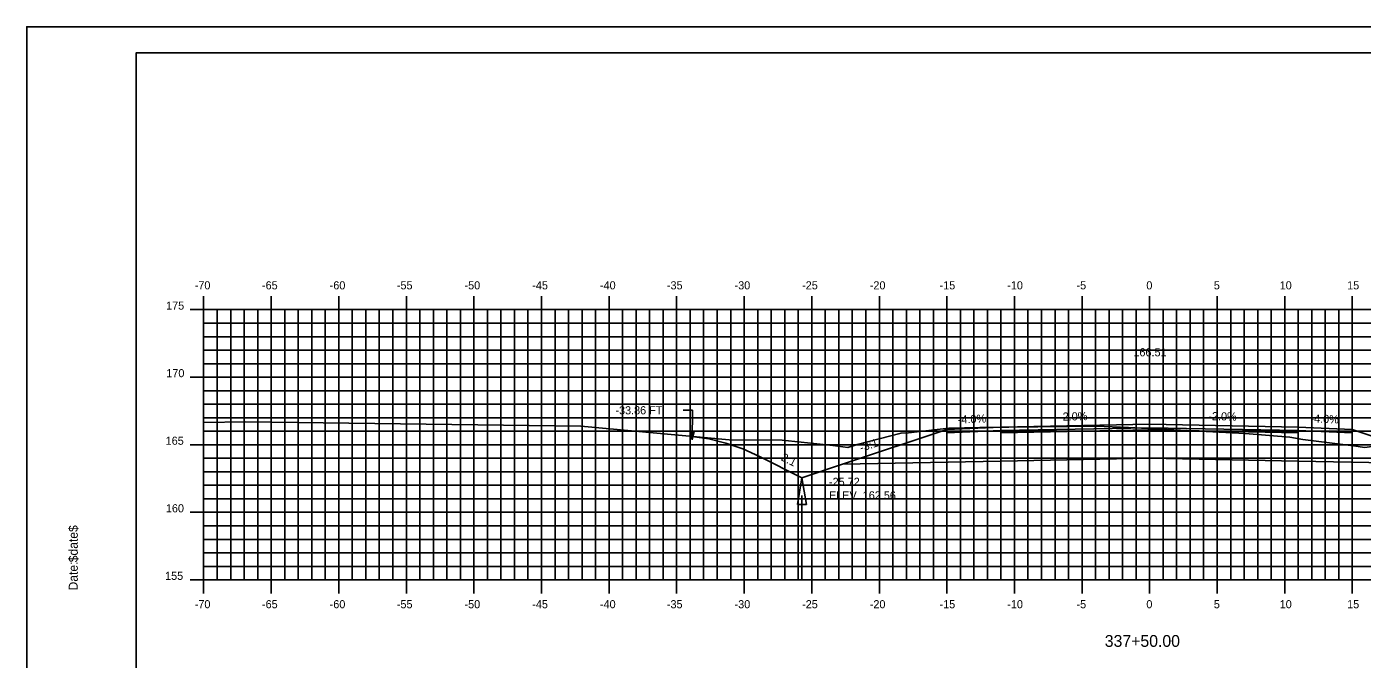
# Model space of a CAD drawing. Extents: x 1142311 to 1142481, y 608981 to 609091.
# Drawn here: x 1142311.2 to 1142410, y 609044.5 to 609091.3 of the extents above; entities that cross this region are included whole.
import ezdxf

# ---------------------------------------------------------------- set-up
doc = ezdxf.new("R2010")
doc.units = 0
for name, color, linetype in [('ANNOTATION', 7, 'Continuous'), ('BORDER', 7, 'Continuous'), ('D_Drainage_Ditch_Line', 7, 'Continuous'), ('D_Roadway_Centerline', 7, 'Continuous'), ('D_Roadway_Centerline_Text', 7, 'Continuous'), ('D_Roadway_Edge_Shoulder', 7, 'Continuous'), ('D_Roadway_Edge_TW', 7, 'Continuous'), ('D_Roadway_Pavement', 7, 'Continuous'), ('D_Roadway_SlopeLines', 7, 'Continuous'), ('D_Roadway_SubGrade', 7, 'Continuous'), ('D_Text_Standard', 7, 'Continuous'), ('H_V ANNOTATION', 7, 'Continuous'), ('MAJOR', 7, 'Continuous'), ('MINOR', 7, 'Continuous'), ('PLOT BOUNDARY', 7, 'Continuous'), ('S_Roadway_Centerline', 7, 'Continuous')]:
    doc.layers.add(name, color=color, linetype=linetype)

msp = doc.modelspace()

# ---------------------------------------------------------------- linework, layer by layer
msp.add_lwpolyline([(1142360.44, 609060.945), (1142361.69, 609060.764), (1142362.94, 609060.457), (1142364.19, 609060.022), (1142365.44, 609059.46), (1142368.572, 609057.894), (1142371.572, 609058.894), (1142379.296, 609061.469), (1142379.297, 609061.469), (1142383.297, 609061.629), (1142394.297, 609061.849), (1142405.297, 609061.629), (1142409.297, 609061.469), (1142417.02, 609058.895), (1142420.02, 609057.895), (1142424.217, 609059.993), (1142425.467, 609060.535), (1142426.717, 609060.911), (1142427.967, 609061.121), (1142429.217, 609061.165)])
at = {"layer": 'BORDER'}
msp.add_lwpolyline([(1142319.297, 608984.335), (1142479.297, 608984.335), (1142479.297, 609089.335), (1142319.297, 609089.335)], close=True, dxfattribs=at)
at = {"layer": 'D_Drainage_Ditch_Line'}
msp.add_line((1142368.572, 609056.582), (1142368.572, 609050.339), dxfattribs=at)
msp.add_lwpolyline([(1142368.9, 609055.926), (1142368.244, 609055.926), (1142368.572, 609057.894)], close=True, dxfattribs=at)
at = {"layer": 'D_Roadway_Edge_Shoulder'}
for points in [[(1142383.297, 609061.629), (1142379.297, 609061.469), (1142379.297, 609061.219), (1142383.297, 609061.379)], [(1142405.297, 609061.629), (1142409.297, 609061.469), (1142409.297, 609061.219), (1142405.297, 609061.379)]]:
    msp.add_lwpolyline(points, close=True, dxfattribs=at)
at = {"layer": 'D_Roadway_Edge_TW'}
msp.add_lwpolyline([(1142383.297, 609061.379), (1142383.297, 609061.629), (1142394.297, 609061.849), (1142405.297, 609061.629), (1142405.297, 609061.379), (1142394.297, 609061.599)], close=True, dxfattribs=at)
at = {"layer": 'D_Roadway_Pavement'}
msp.add_lwpolyline([(1142383.297, 609061.212), (1142383.297, 609061.379), (1142394.297, 609061.599), (1142405.297, 609061.379), (1142405.297, 609061.212), (1142394.297, 609061.432)], close=True, dxfattribs=at)
at = {"layer": 'D_Roadway_SlopeLines'}
for points in [[(1142368.572, 609057.894), (1142365.44, 609059.46), (1142364.19, 609060.022), (1142362.94, 609060.457), (1142361.69, 609060.764), (1142360.44, 609060.945)], [(1142371.572, 609058.894), (1142368.572, 609057.894)]]:
    msp.add_lwpolyline(points, dxfattribs=at)
at = {"layer": 'D_Roadway_SubGrade'}
for points in [[(1142383.297, 609061.212), (1142383.297, 609061.379), (1142379.297, 609061.219), (1142379.297, 609061.469), (1142379.296, 609061.469), (1142371.572, 609058.894), (1142383.297, 609059.129)], [(1142383.297, 609059.129), (1142383.297, 609061.212), (1142394.297, 609061.432), (1142405.297, 609061.212), (1142405.297, 609059.129), (1142394.297, 609059.349)], [(1142405.297, 609061.212), (1142405.297, 609061.379), (1142409.297, 609061.219), (1142409.297, 609061.469), (1142409.297, 609061.469), (1142417.02, 609058.895), (1142405.297, 609059.129)]]:
    msp.add_lwpolyline(points, close=True, dxfattribs=at)
at = {"layer": 'D_Text_Standard'}
msp.add_lwpolyline([(1142360.44, 609060.71), (1142360.462, 609062.888), (1142359.782, 609062.888)], dxfattribs=at)
msp.add_lwpolyline([(1142360.44, 609060.71), (1142360.301, 609061.294), (1142360.592, 609061.291)], close=True, dxfattribs=at)
at = {"layer": 'MAJOR'}
for p, q in [((1142324.297, 609071.337), (1142324.297, 609070.335)), ((1142329.297, 609071.337), (1142329.297, 609070.335)), ((1142334.297, 609071.337), (1142334.297, 609070.335)), ((1142339.297, 609071.337), (1142339.297, 609070.335)), ((1142344.297, 609071.337), (1142344.297, 609070.335)), ((1142349.297, 609071.337), (1142349.297, 609070.335)), ((1142354.297, 609071.337), (1142354.297, 609070.335)), ((1142359.297, 609071.337), (1142359.297, 609070.335)), ((1142364.297, 609071.337), (1142364.297, 609070.335)), ((1142369.297, 609071.337), (1142369.297, 609070.335)), ((1142374.297, 609071.337), (1142374.297, 609070.335)), ((1142379.297, 609071.337), (1142379.297, 609070.335)), ((1142384.297, 609071.337), (1142384.297, 609070.335)), ((1142389.297, 609071.337), (1142389.297, 609070.335)), ((1142394.297, 609071.337), (1142394.297, 609070.335)), ((1142399.297, 609071.337), (1142399.297, 609070.335)), ((1142404.297, 609071.337), (1142404.297, 609070.335)), ((1142409.297, 609071.337), (1142409.297, 609070.335)), ((1142323.295, 609070.335), (1142324.297, 609070.335)), ((1142324.297, 609070.335), (1142464.297, 609070.335)), ((1142324.297, 609050.335), (1142324.297, 609070.335)), ((1142324.297, 609050.335), (1142324.297, 609070.335)), ((1142324.297, 609070.335), (1142464.297, 609070.335)), ((1142329.297, 609050.335), (1142329.297, 609070.335)), ((1142334.297, 609050.335), (1142334.297, 609070.335)), ((1142339.297, 609050.335), (1142339.297, 609070.335)), ((1142344.297, 609050.335), (1142344.297, 609070.335)), ((1142349.297, 609050.335), (1142349.297, 609070.335)), ((1142354.297, 609050.335), (1142354.297, 609070.335)), ((1142359.297, 609050.335), (1142359.297, 609070.335)), ((1142364.297, 609050.335), (1142364.297, 609070.335)), ((1142369.297, 609050.335), (1142369.297, 609070.335)), ((1142374.297, 609050.335), (1142374.297, 609070.335)), ((1142379.297, 609050.335), (1142379.297, 609070.335)), ((1142384.297, 609050.335), (1142384.297, 609070.335)), ((1142389.297, 609050.335), (1142389.297, 609070.335)), ((1142394.297, 609050.335), (1142394.297, 609070.335)), ((1142399.297, 609050.335), (1142399.297, 609070.335)), ((1142404.297, 609050.335), (1142404.297, 609070.335)), ((1142409.297, 609050.335), (1142409.297, 609070.335)), ((1142323.295, 609065.335), (1142324.297, 609065.335)), ((1142324.297, 609065.335), (1142464.297, 609065.335)), ((1142323.295, 609060.335), (1142324.297, 609060.335)), ((1142324.297, 609060.335), (1142464.297, 609060.335)), ((1142323.295, 609055.335), (1142324.297, 609055.335)), ((1142324.297, 609055.335), (1142464.297, 609055.335)), ((1142323.295, 609050.335), (1142324.297, 609050.335)), ((1142324.297, 609050.335), (1142464.297, 609050.335)), ((1142324.297, 609050.335), (1142464.297, 609050.335)), ((1142324.297, 609049.333), (1142324.297, 609050.335)), ((1142329.297, 609049.333), (1142329.297, 609050.335)), ((1142334.297, 609049.333), (1142334.297, 609050.335)), ((1142339.297, 609049.333), (1142339.297, 609050.335)), ((1142344.297, 609049.333), (1142344.297, 609050.335)), ((1142349.297, 609049.333), (1142349.297, 609050.335)), ((1142354.297, 609049.333), (1142354.297, 609050.335)), ((1142359.297, 609049.333), (1142359.297, 609050.335)), ((1142364.297, 609049.333), (1142364.297, 609050.335)), ((1142369.297, 609049.333), (1142369.297, 609050.335)), ((1142374.297, 609049.333), (1142374.297, 609050.335)), ((1142379.297, 609049.333), (1142379.297, 609050.335)), ((1142384.297, 609049.333), (1142384.297, 609050.335)), ((1142389.297, 609049.333), (1142389.297, 609050.335)), ((1142394.297, 609049.333), (1142394.297, 609050.335)), ((1142399.297, 609049.333), (1142399.297, 609050.335)), ((1142404.297, 609049.333), (1142404.297, 609050.335)), ((1142409.297, 609049.333), (1142409.297, 609050.335))]:
    msp.add_line(p, q, dxfattribs=at)
at = {"layer": 'MINOR'}
for p, q in [((1142325.297, 609050.335), (1142325.297, 609070.335)), ((1142326.297, 609050.335), (1142326.297, 609070.335)), ((1142327.297, 609050.335), (1142327.297, 609070.335)), ((1142328.297, 609050.335), (1142328.297, 609070.335)), ((1142330.297, 609050.335), (1142330.297, 609070.335)), ((1142331.297, 609050.335), (1142331.297, 609070.335)), ((1142332.297, 609050.335), (1142332.297, 609070.335)), ((1142333.297, 609050.335), (1142333.297, 609070.335)), ((1142335.297, 609050.335), (1142335.297, 609070.335)), ((1142336.297, 609050.335), (1142336.297, 609070.335)), ((1142337.297, 609050.335), (1142337.297, 609070.335)), ((1142338.297, 609050.335), (1142338.297, 609070.335)), ((1142340.297, 609050.335), (1142340.297, 609070.335)), ((1142341.297, 609050.335), (1142341.297, 609070.335)), ((1142342.297, 609050.335), (1142342.297, 609070.335)), ((1142343.297, 609050.335), (1142343.297, 609070.335)), ((1142345.297, 609050.335), (1142345.297, 609070.335)), ((1142346.297, 609050.335), (1142346.297, 609070.335)), ((1142347.297, 609050.335), (1142347.297, 609070.335)), ((1142348.297, 609050.335), (1142348.297, 609070.335)), ((1142350.297, 609050.335), (1142350.297, 609070.335)), ((1142351.297, 609050.335), (1142351.297, 609070.335)), ((1142352.297, 609050.335), (1142352.297, 609070.335)), ((1142353.297, 609050.335), (1142353.297, 609070.335)), ((1142355.297, 609050.335), (1142355.297, 609070.335)), ((1142356.297, 609050.335), (1142356.297, 609070.335)), ((1142357.297, 609050.335), (1142357.297, 609070.335)), ((1142358.297, 609050.335), (1142358.297, 609070.335)), ((1142360.297, 609050.335), (1142360.297, 609070.335)), ((1142361.297, 609050.335), (1142361.297, 609070.335)), ((1142362.297, 609050.335), (1142362.297, 609070.335)), ((1142363.297, 609050.335), (1142363.297, 609070.335)), ((1142365.297, 609050.335), (1142365.297, 609070.335)), ((1142366.297, 609050.335), (1142366.297, 609070.335)), ((1142367.297, 609050.335), (1142367.297, 609070.335)), ((1142368.297, 609050.335), (1142368.297, 609070.335)), ((1142370.297, 609050.335), (1142370.297, 609070.335)), ((1142371.297, 609050.335), (1142371.297, 609070.335)), ((1142372.297, 609050.335), (1142372.297, 609070.335)), ((1142373.297, 609050.335), (1142373.297, 609070.335)), ((1142375.297, 609050.335), (1142375.297, 609070.335)), ((1142376.297, 609050.335), (1142376.297, 609070.335)), ((1142377.297, 609050.335), (1142377.297, 609070.335)), ((1142378.297, 609050.335), (1142378.297, 609070.335)), ((1142380.297, 609050.335), (1142380.297, 609070.335)), ((1142381.297, 609050.335), (1142381.297, 609070.335)), ((1142382.297, 609050.335), (1142382.297, 609070.335)), ((1142383.297, 609050.335), (1142383.297, 609070.335)), ((1142385.297, 609050.335), (1142385.297, 609070.335)), ((1142386.297, 609050.335), (1142386.297, 609070.335)), ((1142387.297, 609050.335), (1142387.297, 609070.335)), ((1142388.297, 609050.335), (1142388.297, 609070.335)), ((1142390.297, 609050.335), (1142390.297, 609070.335)), ((1142391.297, 609050.335), (1142391.297, 609070.335)), ((1142392.297, 609050.335), (1142392.297, 609070.335)), ((1142393.297, 609050.335), (1142393.297, 609070.335)), ((1142395.297, 609050.335), (1142395.297, 609070.335)), ((1142396.297, 609050.335), (1142396.297, 609070.335)), ((1142397.297, 609050.335), (1142397.297, 609070.335)), ((1142398.297, 609050.335), (1142398.297, 609070.335)), ((1142400.297, 609050.335), (1142400.297, 609070.335)), ((1142401.297, 609050.335), (1142401.297, 609070.335)), ((1142402.297, 609050.335), (1142402.297, 609070.335)), ((1142403.297, 609050.335), (1142403.297, 609070.335)), ((1142405.297, 609050.335), (1142405.297, 609070.335)), ((1142406.297, 609050.335), (1142406.297, 609070.335)), ((1142407.297, 609050.335), (1142407.297, 609070.335)), ((1142408.297, 609050.335), (1142408.297, 609070.335)), ((1142324.297, 609069.335), (1142464.297, 609069.335)), ((1142324.297, 609069.335), (1142325.299, 609069.335)), ((1142324.297, 609068.335), (1142464.297, 609068.335)), ((1142324.297, 609068.335), (1142325.299, 609068.335)), ((1142324.297, 609067.335), (1142464.297, 609067.335)), ((1142324.297, 609067.335), (1142325.299, 609067.335)), ((1142324.297, 609066.335), (1142464.297, 609066.335)), ((1142324.297, 609066.335), (1142325.299, 609066.335)), ((1142324.297, 609064.335), (1142464.297, 609064.335)), ((1142324.297, 609064.335), (1142325.299, 609064.335)), ((1142324.297, 609063.335), (1142464.297, 609063.335)), ((1142324.297, 609063.335), (1142325.299, 609063.335)), ((1142324.297, 609062.335), (1142464.297, 609062.335)), ((1142324.297, 609062.335), (1142325.299, 609062.335)), ((1142324.297, 609061.335), (1142464.297, 609061.335)), ((1142324.297, 609061.335), (1142325.299, 609061.335)), ((1142324.297, 609059.335), (1142464.297, 609059.335)), ((1142324.297, 609059.335), (1142325.299, 609059.335)), ((1142324.297, 609058.335), (1142464.297, 609058.335)), ((1142324.297, 609058.335), (1142325.299, 609058.335)), ((1142324.297, 609057.335), (1142464.297, 609057.335)), ((1142324.297, 609057.335), (1142325.299, 609057.335)), ((1142324.297, 609056.335), (1142464.297, 609056.335)), ((1142324.297, 609056.335), (1142325.299, 609056.335)), ((1142324.297, 609054.335), (1142464.297, 609054.335)), ((1142324.297, 609054.335), (1142325.299, 609054.335)), ((1142324.297, 609053.335), (1142464.297, 609053.335)), ((1142324.297, 609053.335), (1142325.299, 609053.335)), ((1142324.297, 609052.335), (1142464.297, 609052.335)), ((1142324.297, 609052.335), (1142325.299, 609052.335)), ((1142324.297, 609051.335), (1142464.297, 609051.335)), ((1142324.297, 609051.335), (1142325.299, 609051.335))]:
    msp.add_line(p, q, dxfattribs=at)
at = {"layer": 'PLOT BOUNDARY'}
msp.add_lwpolyline([(1142311.204, 608981.276), (1142481.204, 608981.276), (1142481.204, 609091.276), (1142311.204, 609091.276)], close=True, dxfattribs=at)
at = {"layer": 'S_Roadway_Centerline'}
msp.add_lwpolyline([(1142324.297, 609061.986), (1142327.43, 609062.024), (1142352.199, 609061.719), (1142363.18, 609060.688), (1142367.114, 609060.687), (1142370.862, 609060.287), (1142371.956, 609060.13), (1142372.66, 609060.351), (1142375.902, 609061.195), (1142376.467, 609061.226), (1142379.436, 609061.552), (1142381.746, 609061.614), (1142390.352, 609061.701), (1142392.745, 609061.612), (1142401.374, 609061.166), (1142404.67, 609060.907), (1142405.628, 609060.736), (1142409.38, 609060.244), (1142410.227, 609060.138), (1142412.74, 609060.5), (1142417.98, 609061.507), (1142428.434, 609061.191), (1142446.865, 609060.587)], dxfattribs=at)

# ---------------------------------------------------------------- texts
at = {"layer": 'ANNOTATION'}
for s, rotation, p in [('-4.0%', 2.29061, (1142380.113, 609061.902)), ('-2.0%', 1.14576, (1142387.6, 609062.115)), ('-2.0%', 358.85424, (1142398.64, 609062.162)), ('-4.0%', 357.70939, (1142406.193, 609061.994)), ('-3:1', 18.43482, (1142372.951, 609059.808)), ('2:1', 333.43495, (1142366.973, 609059.212))]:
    msp.add_text(s, height=0.6, rotation=rotation, dxfattribs=at).set_placement(p)
at = {"layer": 'BORDER'}
for s, p in [('$date$', (1142314.982, 609051.64)), ('Date:', (1142314.982, 609049.552))]:
    msp.add_text(s, height=0.6696, rotation=90, dxfattribs=at).set_placement(p)
at = {"layer": 'D_Roadway_Centerline'}
for s, p in [('C', (1142394.292, 609061.849)), ('L', (1142394.297, 609061.842))]:
    msp.add_text(s, height=0.0146, dxfattribs=at).set_placement(p)
at = {"layer": 'D_Roadway_Centerline_Text'}
msp.add_text('166.51', height=0.6, dxfattribs=at).set_placement((1142393.098, 609066.881))
at = {"layer": 'D_Text_Standard'}
for s, p in [('-33.86 FT', (1142354.767, 609062.588)), ('-25.72', (1142370.572, 609057.294)), ('ELEV. 162.56', (1142370.572, 609056.292))]:
    msp.add_text(s, height=0.6, dxfattribs=at).set_placement(p)
at = {"layer": 'H_V ANNOTATION'}
for s, height, p in [('-70', 0.6, (1142323.638, 609071.835)), ('-65', 0.6, (1142328.615, 609071.835)), ('-60', 0.6, (1142333.623, 609071.835)), ('-55', 0.6, (1142338.593, 609071.835)), ('-50', 0.6, (1142343.601, 609071.835)), ('-45', 0.6, (1142348.615, 609071.835)), ('-40', 0.6, (1142353.623, 609071.835)), ('-35', 0.6, (1142358.577, 609071.835)), ('-30', 0.6, (1142363.585, 609071.835)), ('-25', 0.6, (1142368.582, 609071.835)), ('-20', 0.6, (1142373.59, 609071.835)), ('-15', 0.6, (1142378.754, 609071.835)), ('-10', 0.6, (1142383.762, 609071.835)), ('-5', 0.6, (1142388.887, 609071.835)), ('0', 0.6, (1142394.056, 609071.835)), ('5', 0.6, (1142399.048, 609071.835)), ('10', 0.6, (1142403.922, 609071.835)), ('15', 0.6, (1142408.914, 609071.835)), ('175', 0.6, (1142321.518, 609070.335)), ('170', 0.6, (1142321.534, 609065.335)), ('165', 0.6, (1142321.486, 609060.335)), ('160', 0.6, (1142321.502, 609055.335)), ('155', 0.6, (1142321.443, 609050.335)), ('-70', 0.6, (1142323.638, 609048.235)), ('-65', 0.6, (1142328.615, 609048.235)), ('-60', 0.6, (1142333.623, 609048.235)), ('-55', 0.6, (1142338.593, 609048.235)), ('-50', 0.6, (1142343.601, 609048.235)), ('-45', 0.6, (1142348.615, 609048.235)), ('-40', 0.6, (1142353.623, 609048.235)), ('-35', 0.6, (1142358.577, 609048.235)), ('-30', 0.6, (1142363.585, 609048.235)), ('-25', 0.6, (1142368.582, 609048.235)), ('-20', 0.6, (1142373.59, 609048.235)), ('-15', 0.6, (1142378.754, 609048.235)), ('-10', 0.6, (1142383.762, 609048.235)), ('-5', 0.6, (1142388.887, 609048.235)), ('0', 0.6, (1142394.056, 609048.235)), ('5', 0.6, (1142399.048, 609048.235)), ('10', 0.6, (1142403.922, 609048.235)), ('15', 0.6, (1142408.914, 609048.235)), ('337+50.00', 0.875, (1142390.98, 609045.378))]:
    msp.add_text(s, height=height, dxfattribs=at).set_placement(p)
at = {"layer": 'MAJOR'}
msp.add_text('-', height=0.006, dxfattribs=at).set_placement((1142324.292, 609050.335))
at = {"layer": 'S_Roadway_Centerline'}
for s, p in [('L', (1142390.344, 609061.694)), ('C', (1142390.347, 609061.701))]:
    msp.add_text(s, height=0.0146, dxfattribs=at).set_placement(p)

doc.saveas('drawing.dxf')
